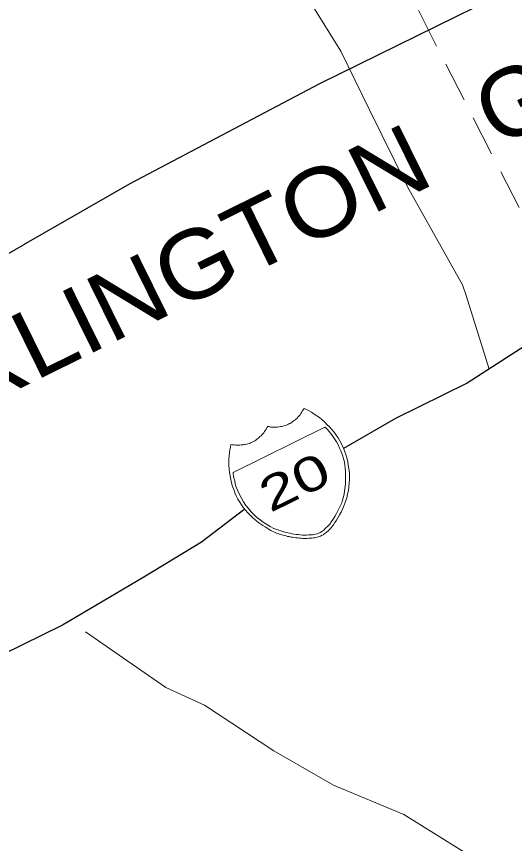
# Model space of a CAD drawing. Extents: x 2356606 to 2371222, y 6973096 to 6982644.
# Drawn here: x 2370977.6 to 2371051.8, y 6980347 to 6980470.1 of the extents above; entities that cross this region are included whole.
import ezdxf

# ---------------------------------------------------------------- set-up
doc = ezdxf.new("R2010")
doc.units = 0
doc.header["$LTSCALE"] = 2
doc.linetypes.add('MEDIUM_DASHED', pattern=[4.5, 3, -1.5])
doc.layers.add('62', color=7, linetype='Continuous', lineweight=13)
doc.layers.add('63', color=7, linetype='Continuous', lineweight=13)

msp = doc.modelspace()

# ---------------------------------------------------------------- linework, layer by layer
at = {"layer": '62', "linetype": 'MEDIUM_DASHED'}
msp.add_line((2370972, 6980599.301), (2371099.701, 6980348.989), dxfattribs=at)
at = {"layer": '62'}
for p, q in [((2371025.887, 6980464.899), (2371019.329, 6980475.488)), ((2371044.002, 6980430.128), (2371044.557, 6980428.546)), ((2371044.557, 6980428.546), (2371047.981, 6980417.586))]:
    msp.add_line(p, q, dxfattribs=at)
at = {"layer": '62', "lineweight": 25}
msp.add_line((2370958.804, 6980424.741), (2370978.671, 6980436.103), dxfattribs=at)
for points in [[(2371119.806, 6980516.871), (2371108.589, 6980509.904), (2371091.896, 6980498.532), (2371071.569, 6980485.363), (2371048.771, 6980472.932), (2371022.721, 6980460.075), (2370994.479, 6980445.157), (2370978.671, 6980436.103)], [(2371151.844, 6980451.959), (2371136.822, 6980452.699), (2371120.015, 6980448.521), (2371102.607, 6980445.048), (2371080.793, 6980435.46), (2371067.811, 6980430.032), (2371059.219, 6980424.813), (2371044.719, 6980415.501), (2371034.045, 6980410.232), (2371026.295, 6980405.753)], [(2371011.483, 6980396.661), (2371005.138, 6980391.825), (2370996.569, 6980386.616), (2370984.445, 6980379.452), (2370975.486, 6980375.033), (2370969.457, 6980371.078), (2370966.224, 6980366.347), (2370958.11, 6980360.159), (2370945.05, 6980354.893), (2370933.131, 6980350.014), (2370920.141, 6980344.556), (2370901.53, 6980332.234), (2370881.498, 6980325.485), (2370864.621, 6980321.497), (2370853.225, 6980321.969), (2370844.613, 6980332.451), (2370838.758, 6980344.313), (2370834.175, 6980349.329), (2370834.503, 6980359.904)]]:
    msp.add_lwpolyline(points, dxfattribs=at)
at = {"layer": '62'}
for points in [[(2371025.887, 6980464.899), (2371030.187, 6980456.181), (2371035.836, 6980444.74), (2371044.002, 6980430.128)], [(2371015.855, 6980408.957), (2371016.086, 6980408.945), (2371016.289, 6980408.945), (2371016.479, 6980408.963), (2371016.701, 6980408.973), (2371016.894, 6980409.043), (2371017.074, 6980409.031), (2371017.267, 6980409.1), (2371017.447, 6980409.139), (2371017.647, 6980409.189), (2371017.82, 6980409.25), (2371018.001, 6980409.339), (2371018.182, 6980409.429), (2371018.344, 6980409.508), (2371018.505, 6980409.588), (2371018.677, 6980409.697), (2371018.82, 6980409.818), (2371018.962, 6980409.936), (2371019.133, 6980410.046), (2371019.255, 6980410.207), (2371019.406, 6980410.307), (2371019.547, 6980410.478), (2371019.698, 6980410.628), (2371019.822, 6980410.789), (2371019.932, 6980410.968), (2371020.053, 6980411.128), (2371020.164, 6980411.31), (2371020.307, 6980411.532), (2371020.417, 6980411.711), (2371020.772, 6980411.558), (2371021.162, 6980411.376), (2371021.542, 6980411.163), (2371021.924, 6980410.899), (2371022.304, 6980410.635), (2371022.717, 6980410.36), (2371023.086, 6980410.067), (2371023.479, 6980409.732), (2371023.839, 6980409.359), (2371024.198, 6980408.985), (2371024.569, 6980408.591), (2371024.899, 6980408.175), (2371025.21, 6980407.752), (2371025.487, 6980407.335), (2371025.759, 6980406.894), (2371026.007, 6980406.44), (2371026.235, 6980405.925), (2371026.445, 6980405.399), (2371026.634, 6980404.868), (2371026.8, 6980404.373), (2371026.939, 6980403.839), (2371027.017, 6980403.273), (2371027.104, 6980402.74), (2371027.193, 6980402.207), (2371027.199, 6980401.684), (2371027.178, 6980401.122), (2371027.163, 6980400.587), (2371027.101, 6980400.054), (2371027.028, 6980399.491), (2371026.914, 6980398.959), (2371026.77, 6980398.436), (2371026.595, 6980397.873), (2371026.444, 6980397.47), (2371026.289, 6980397.07), (2371026.118, 6980396.658), (2371025.934, 6980396.266), (2371025.701, 6980395.877), (2371025.476, 6980395.465), (2371025.253, 6980395.103), (2371025.019, 6980394.762), (2371024.788, 6980394.423), (2371024.543, 6980394.101), (2371024.29, 6980393.8), (2371023.995, 6980393.529), (2371023.774, 6980393.318), (2371023.5, 6980393.109), (2371023.268, 6980392.919), (2371023.025, 6980392.798)], [(2371023.025, 6980392.798), (2371022.865, 6980392.72), (2371022.723, 6980392.65), (2371022.523, 6980392.602), (2371022.37, 6980392.551), (2371022.21, 6980392.523), (2371021.998, 6980392.492), (2371021.796, 6980392.444), (2371021.586, 6980392.415), (2371021.365, 6980392.406), (2371021.142, 6980392.397), (2371020.902, 6980392.377), (2371020.7, 6980392.379), (2371020.447, 6980392.381), (2371020.215, 6980392.391), (2371019.986, 6980392.403), (2371019.734, 6980392.403), (2371019.483, 6980392.455), (2371019.22, 6980392.477), (2371018.96, 6980392.498), (2371018.727, 6980392.558), (2371018.486, 6980392.59), (2371018.227, 6980392.663), (2371017.965, 6980392.683), (2371017.752, 6980392.757), (2371017.502, 6980392.808), (2371017.269, 6980392.869), (2371017.01, 6980392.941), (2371016.791, 6980393.033), (2371016.548, 6980393.114), (2371016.336, 6980393.186), (2371016.148, 6980393.27), (2371015.913, 6980393.379), (2371015.494, 6980393.574), (2371015.073, 6980393.816), (2371014.644, 6980394.081), (2371014.269, 6980394.324), (2371013.858, 6980394.597), (2371013.458, 6980394.902), (2371013.086, 6980395.193), (2371012.725, 6980395.519), (2371012.385, 6980395.851), (2371012.035, 6980396.207), (2371011.724, 6980396.58), (2371011.414, 6980396.955), (2371011.115, 6980397.357), (2371010.856, 6980397.782), (2371010.574, 6980398.245), (2371010.327, 6980398.701), (2371010.137, 6980399.184), (2371009.949, 6980399.669), (2371009.772, 6980400.133), (2371009.643, 6980400.647), (2371009.516, 6980401.162), (2371009.406, 6980401.683), (2371009.328, 6980402.198), (2371009.251, 6980402.71), (2371009.223, 6980403.225), (2371009.215, 6980403.696), (2371009.228, 6980404.181), (2371009.271, 6980404.654), (2371009.313, 6980405.126), (2371009.358, 6980405.55), (2371009.451, 6980405.971), (2371009.544, 6980406.343), (2371009.775, 6980406.332), (2371010.017, 6980406.302), (2371010.247, 6980406.288), (2371010.43, 6980406.279), (2371010.659, 6980406.266), (2371010.861, 6980406.265), (2371011.071, 6980406.295), (2371011.294, 6980406.304), (2371011.466, 6980406.363), (2371011.667, 6980406.362), (2371011.859, 6980406.433), (2371012.039, 6980406.471), (2371012.238, 6980406.52), (2371012.411, 6980406.58), (2371012.574, 6980406.661), (2371012.776, 6980406.758), (2371012.915, 6980406.829), (2371013.099, 6980406.918), (2371013.25, 6980407.017), (2371013.411, 6980407.149), (2371013.555, 6980407.268), (2371013.706, 6980407.369), (2371013.848, 6980407.538), (2371014.016, 6980407.648), (2371014.118, 6980407.799), (2371014.272, 6980407.948), (2371014.413, 6980408.118), (2371014.546, 6980408.311), (2371014.646, 6980408.461), (2371014.778, 6980408.649), (2371014.879, 6980408.85), (2371015.012, 6980409.043), (2371015.221, 6980409.02), (2371015.422, 6980408.967), (2371015.655, 6980408.959), (2371015.855, 6980408.957)], [(2371147.148, 6980328.917), (2371138.571, 6980328.048), (2371129.118, 6980325.438), (2371112.027, 6980320.969), (2371100.06, 6980322.039), (2371091.911, 6980322.932), (2371081.3, 6980324.295), (2371069.258, 6980328.819), (2371059.239, 6980335.242), (2371048.852, 6980342.862), (2371035.27, 6980351.267), (2371024.817, 6980355.667), (2371015.947, 6980360.773), (2371005.588, 6980367.578), (2370999.855, 6980370.196), (2370987.882, 6980378.49)]]:
    msp.add_lwpolyline(points, dxfattribs=at)
msp.add_lwpolyline([(2371023.514, 6980408.947), (2371009.853, 6980402.206), (2371009.892, 6980401.973), (2371009.909, 6980401.681), (2371009.967, 6980401.36), (2371010.097, 6980400.947), (2371010.186, 6980400.513), (2371010.334, 6980400.01), (2371010.542, 6980399.485), (2371010.792, 6980398.93), (2371011.09, 6980398.375), (2371011.408, 6980397.83), (2371011.768, 6980397.305), (2371012.129, 6980396.831), (2371012.538, 6980396.355), (2371012.948, 6980395.93), (2371013.409, 6980395.506), (2371013.871, 6980395.131), (2371014.344, 6980394.788), (2371014.867, 6980394.442), (2371015.387, 6980394.147), (2371015.95, 6980393.874), (2371016.541, 6980393.638), (2371017.112, 6980393.444), (2371017.727, 6980393.27), (2371018.339, 6980393.145), (2371018.641, 6980393.044), (2371018.951, 6980393.021), (2371019.253, 6980392.97), (2371019.586, 6980392.959), (2371019.858, 6980392.915), (2371020.179, 6980392.875), (2371020.482, 6980392.874), (2371020.802, 6980392.881), (2371021.074, 6980392.891), (2371021.366, 6980392.909), (2371021.66, 6980392.928), (2371021.891, 6980392.966), (2371022.141, 6980393.016), (2371022.364, 6980393.074), (2371022.606, 6980393.145), (2371022.808, 6980393.242), (2371023.08, 6980393.404), (2371023.393, 6980393.634), (2371023.637, 6980393.903), (2371023.958, 6980394.214), (2371024.245, 6980394.505), (2371024.488, 6980394.877), (2371024.751, 6980395.256), (2371025.006, 6980395.657), (2371025.248, 6980396.079), (2371025.453, 6980396.482), (2371025.655, 6980396.882), (2371025.849, 6980397.302), (2371026.032, 6980397.694), (2371026.144, 6980398.077), (2371026.269, 6980398.439), (2371026.329, 6980398.77), (2371026.433, 6980399.324), (2371026.505, 6980399.887), (2371026.58, 6980400.4), (2371026.603, 6980400.963), (2371026.614, 6980401.446), (2371026.606, 6980401.918), (2371026.6, 6980402.392), (2371026.541, 6980402.864), (2371026.483, 6980403.339), (2371026.425, 6980403.763), (2371026.307, 6980404.205), (2371026.178, 6980404.616), (2371026.03, 6980405.02), (2371025.901, 6980405.434), (2371025.713, 6980405.816), (2371025.543, 6980406.21), (2371025.254, 6980406.745), (2371024.966, 6980407.231), (2371024.674, 6980407.663), (2371024.425, 6980408.018), (2371024.135, 6980408.35), (2371023.894, 6980408.583), (2371023.695, 6980408.785)], close=True, dxfattribs=at)
at = {"layer": '63', "linetype": 'MEDIUM_DASHED'}
msp.add_line((2370972, 6980599.301), (2371099.701, 6980348.989), dxfattribs=at)
at = {"layer": '63'}
for p, q in [((2371025.887, 6980464.899), (2371019.329, 6980475.488)), ((2371044.002, 6980430.128), (2371044.557, 6980428.546)), ((2371044.557, 6980428.546), (2371047.981, 6980417.586))]:
    msp.add_line(p, q, dxfattribs=at)
at = {"layer": '63', "lineweight": 25}
msp.add_line((2370958.804, 6980424.741), (2370978.671, 6980436.103), dxfattribs=at)
for points in [[(2371119.806, 6980516.871), (2371108.589, 6980509.904), (2371091.896, 6980498.532), (2371071.569, 6980485.363), (2371048.771, 6980472.932), (2371022.721, 6980460.075), (2370994.479, 6980445.157), (2370978.671, 6980436.103)], [(2371151.844, 6980451.959), (2371136.822, 6980452.699), (2371120.015, 6980448.521), (2371102.607, 6980445.048), (2371080.793, 6980435.46), (2371067.811, 6980430.032), (2371059.219, 6980424.813), (2371044.719, 6980415.501), (2371034.045, 6980410.232), (2371026.295, 6980405.753)], [(2371011.483, 6980396.661), (2371005.138, 6980391.825), (2370996.569, 6980386.616), (2370984.445, 6980379.452), (2370975.486, 6980375.033), (2370969.457, 6980371.078), (2370966.224, 6980366.347), (2370958.11, 6980360.159), (2370945.05, 6980354.893), (2370933.131, 6980350.014), (2370920.141, 6980344.556), (2370901.53, 6980332.234), (2370881.498, 6980325.485), (2370864.621, 6980321.497), (2370853.225, 6980321.969), (2370844.613, 6980332.451), (2370838.758, 6980344.313), (2370834.175, 6980349.329), (2370834.503, 6980359.904)]]:
    msp.add_lwpolyline(points, dxfattribs=at)
at = {"layer": '63'}
for points in [[(2371025.887, 6980464.899), (2371030.187, 6980456.181), (2371035.836, 6980444.74), (2371044.002, 6980430.128)], [(2371015.855, 6980408.957), (2371016.086, 6980408.945), (2371016.289, 6980408.945), (2371016.479, 6980408.963), (2371016.701, 6980408.973), (2371016.894, 6980409.043), (2371017.074, 6980409.031), (2371017.267, 6980409.1), (2371017.447, 6980409.139), (2371017.647, 6980409.189), (2371017.82, 6980409.25), (2371018.001, 6980409.339), (2371018.182, 6980409.429), (2371018.344, 6980409.508), (2371018.505, 6980409.588), (2371018.677, 6980409.697), (2371018.82, 6980409.818), (2371018.962, 6980409.936), (2371019.133, 6980410.046), (2371019.255, 6980410.207), (2371019.406, 6980410.307), (2371019.547, 6980410.478), (2371019.698, 6980410.628), (2371019.822, 6980410.789), (2371019.932, 6980410.968), (2371020.053, 6980411.128), (2371020.164, 6980411.31), (2371020.307, 6980411.532), (2371020.417, 6980411.711), (2371020.772, 6980411.558), (2371021.162, 6980411.376), (2371021.542, 6980411.163), (2371021.924, 6980410.899), (2371022.304, 6980410.635), (2371022.717, 6980410.36), (2371023.086, 6980410.067), (2371023.479, 6980409.732), (2371023.839, 6980409.359), (2371024.198, 6980408.985), (2371024.569, 6980408.591), (2371024.899, 6980408.175), (2371025.21, 6980407.752), (2371025.487, 6980407.335), (2371025.759, 6980406.894), (2371026.007, 6980406.44), (2371026.235, 6980405.925), (2371026.445, 6980405.399), (2371026.634, 6980404.868), (2371026.8, 6980404.373), (2371026.939, 6980403.839), (2371027.017, 6980403.273), (2371027.104, 6980402.74), (2371027.193, 6980402.207), (2371027.199, 6980401.684), (2371027.178, 6980401.122), (2371027.163, 6980400.587), (2371027.101, 6980400.054), (2371027.028, 6980399.491), (2371026.914, 6980398.959), (2371026.77, 6980398.436), (2371026.595, 6980397.873), (2371026.444, 6980397.47), (2371026.289, 6980397.07), (2371026.118, 6980396.658), (2371025.934, 6980396.266), (2371025.701, 6980395.877), (2371025.476, 6980395.465), (2371025.253, 6980395.103), (2371025.019, 6980394.762), (2371024.788, 6980394.423), (2371024.543, 6980394.101), (2371024.29, 6980393.8), (2371023.995, 6980393.529), (2371023.774, 6980393.318), (2371023.5, 6980393.109), (2371023.268, 6980392.919), (2371023.025, 6980392.798)], [(2371023.025, 6980392.798), (2371022.865, 6980392.72), (2371022.723, 6980392.65), (2371022.523, 6980392.602), (2371022.37, 6980392.551), (2371022.21, 6980392.523), (2371021.998, 6980392.492), (2371021.796, 6980392.444), (2371021.586, 6980392.415), (2371021.365, 6980392.406), (2371021.142, 6980392.397), (2371020.902, 6980392.377), (2371020.7, 6980392.379), (2371020.447, 6980392.381), (2371020.215, 6980392.391), (2371019.986, 6980392.403), (2371019.734, 6980392.403), (2371019.483, 6980392.455), (2371019.22, 6980392.477), (2371018.96, 6980392.498), (2371018.727, 6980392.558), (2371018.486, 6980392.59), (2371018.227, 6980392.663), (2371017.965, 6980392.683), (2371017.752, 6980392.757), (2371017.502, 6980392.808), (2371017.269, 6980392.869), (2371017.01, 6980392.941), (2371016.791, 6980393.033), (2371016.548, 6980393.114), (2371016.336, 6980393.186), (2371016.148, 6980393.27), (2371015.913, 6980393.379), (2371015.494, 6980393.574), (2371015.073, 6980393.816), (2371014.644, 6980394.081), (2371014.269, 6980394.324), (2371013.858, 6980394.597), (2371013.458, 6980394.902), (2371013.086, 6980395.193), (2371012.725, 6980395.519), (2371012.385, 6980395.851), (2371012.035, 6980396.207), (2371011.724, 6980396.58), (2371011.414, 6980396.955), (2371011.115, 6980397.357), (2371010.856, 6980397.782), (2371010.574, 6980398.245), (2371010.327, 6980398.701), (2371010.137, 6980399.184), (2371009.949, 6980399.669), (2371009.772, 6980400.133), (2371009.643, 6980400.647), (2371009.516, 6980401.162), (2371009.406, 6980401.683), (2371009.328, 6980402.198), (2371009.251, 6980402.71), (2371009.223, 6980403.225), (2371009.215, 6980403.696), (2371009.228, 6980404.181), (2371009.271, 6980404.654), (2371009.313, 6980405.126), (2371009.358, 6980405.55), (2371009.451, 6980405.971), (2371009.544, 6980406.343), (2371009.775, 6980406.332), (2371010.017, 6980406.302), (2371010.247, 6980406.288), (2371010.43, 6980406.279), (2371010.659, 6980406.266), (2371010.861, 6980406.265), (2371011.071, 6980406.295), (2371011.294, 6980406.304), (2371011.466, 6980406.363), (2371011.667, 6980406.362), (2371011.859, 6980406.433), (2371012.039, 6980406.471), (2371012.238, 6980406.52), (2371012.411, 6980406.58), (2371012.574, 6980406.661), (2371012.776, 6980406.758), (2371012.915, 6980406.829), (2371013.099, 6980406.918), (2371013.25, 6980407.017), (2371013.411, 6980407.149), (2371013.555, 6980407.268), (2371013.706, 6980407.369), (2371013.848, 6980407.538), (2371014.016, 6980407.648), (2371014.118, 6980407.799), (2371014.272, 6980407.948), (2371014.413, 6980408.118), (2371014.546, 6980408.311), (2371014.646, 6980408.461), (2371014.778, 6980408.649), (2371014.879, 6980408.85), (2371015.012, 6980409.043), (2371015.221, 6980409.02), (2371015.422, 6980408.967), (2371015.655, 6980408.959), (2371015.855, 6980408.957)], [(2371147.148, 6980328.917), (2371138.571, 6980328.048), (2371129.118, 6980325.438), (2371112.027, 6980320.969), (2371100.06, 6980322.039), (2371091.911, 6980322.932), (2371081.3, 6980324.295), (2371069.258, 6980328.819), (2371059.239, 6980335.242), (2371048.852, 6980342.862), (2371035.27, 6980351.267), (2371024.817, 6980355.667), (2371015.947, 6980360.773), (2371005.588, 6980367.578), (2370999.855, 6980370.196), (2370987.882, 6980378.49)]]:
    msp.add_lwpolyline(points, dxfattribs=at)
msp.add_lwpolyline([(2371023.514, 6980408.947), (2371009.853, 6980402.206), (2371009.892, 6980401.973), (2371009.909, 6980401.681), (2371009.967, 6980401.36), (2371010.097, 6980400.947), (2371010.186, 6980400.513), (2371010.334, 6980400.01), (2371010.542, 6980399.485), (2371010.792, 6980398.93), (2371011.09, 6980398.375), (2371011.408, 6980397.83), (2371011.768, 6980397.305), (2371012.129, 6980396.831), (2371012.538, 6980396.355), (2371012.948, 6980395.93), (2371013.409, 6980395.506), (2371013.871, 6980395.131), (2371014.344, 6980394.788), (2371014.867, 6980394.442), (2371015.387, 6980394.147), (2371015.95, 6980393.874), (2371016.541, 6980393.638), (2371017.112, 6980393.444), (2371017.727, 6980393.27), (2371018.339, 6980393.145), (2371018.641, 6980393.044), (2371018.951, 6980393.021), (2371019.253, 6980392.97), (2371019.586, 6980392.959), (2371019.858, 6980392.915), (2371020.179, 6980392.875), (2371020.482, 6980392.874), (2371020.802, 6980392.881), (2371021.074, 6980392.891), (2371021.366, 6980392.909), (2371021.66, 6980392.928), (2371021.891, 6980392.966), (2371022.141, 6980393.016), (2371022.364, 6980393.074), (2371022.606, 6980393.145), (2371022.808, 6980393.242), (2371023.08, 6980393.404), (2371023.393, 6980393.634), (2371023.637, 6980393.903), (2371023.958, 6980394.214), (2371024.245, 6980394.505), (2371024.488, 6980394.877), (2371024.751, 6980395.256), (2371025.006, 6980395.657), (2371025.248, 6980396.079), (2371025.453, 6980396.482), (2371025.655, 6980396.882), (2371025.849, 6980397.302), (2371026.032, 6980397.694), (2371026.144, 6980398.077), (2371026.269, 6980398.439), (2371026.329, 6980398.77), (2371026.433, 6980399.324), (2371026.505, 6980399.887), (2371026.58, 6980400.4), (2371026.603, 6980400.963), (2371026.614, 6980401.446), (2371026.606, 6980401.918), (2371026.6, 6980402.392), (2371026.541, 6980402.864), (2371026.483, 6980403.339), (2371026.425, 6980403.763), (2371026.307, 6980404.205), (2371026.178, 6980404.616), (2371026.03, 6980405.02), (2371025.901, 6980405.434), (2371025.713, 6980405.816), (2371025.543, 6980406.21), (2371025.254, 6980406.745), (2371024.966, 6980407.231), (2371024.674, 6980407.663), (2371024.425, 6980408.018), (2371024.135, 6980408.35), (2371023.894, 6980408.583), (2371023.695, 6980408.785)], close=True, dxfattribs=at)

# ---------------------------------------------------------------- texts
at = {"layer": '62'}
for s, height, width, p in [('GRAND', 10.21, 1.05, (2371049.119, 6980450.418)), ('ARLINGTON', 10.21, 1.1, (2370961.602, 6980406.523)), ('20', 5.099, 1.4, (2371015.377, 6980396.151))]:
    msp.add_text(s, height=height, rotation=26.268, dxfattribs=dict(at, width=width)).set_placement(p)
at = {"layer": '63'}
for s, height, width, p in [('GRAND', 10.21, 1.05, (2371049.119, 6980450.418)), ('ARLINGTON', 10.21, 1.1, (2370961.602, 6980406.523)), ('20', 5.099, 1.4, (2371015.377, 6980396.151))]:
    msp.add_text(s, height=height, rotation=26.268, dxfattribs=dict(at, width=width)).set_placement(p)

doc.saveas('drawing.dxf')
